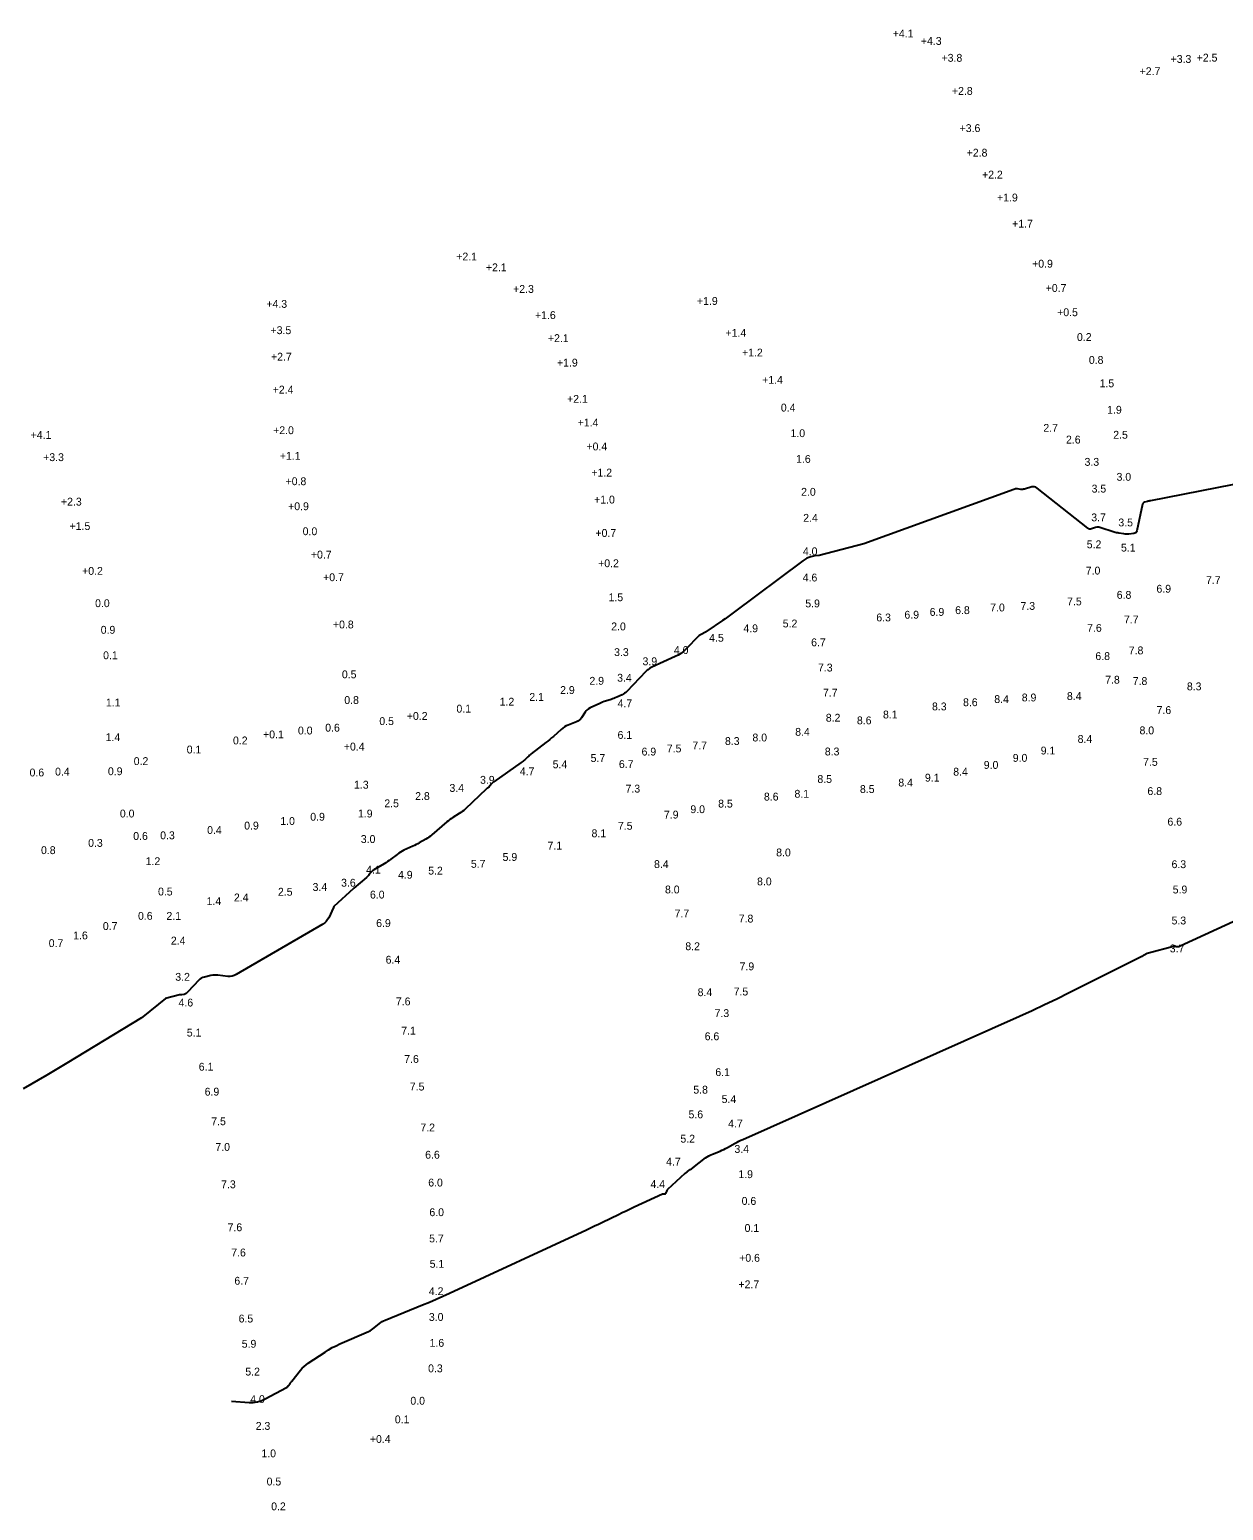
# Model space of a CAD drawing. Extents: x 837127 to 848654, y 3074248 to 3079868.
# Drawn here: x 846810 to 847285, y 3078154 to 3078743 of the extents above; entities that cross this region are included whole.
import ezdxf

# ---------------------------------------------------------------- set-up
doc = ezdxf.new("R2010")
doc.units = 0
doc.layers.add('V-HYDS-MAJR', color=7, linetype='Continuous')
doc.layers.add('V-HYDS-SOUN', color=7, linetype='Continuous')

msp = doc.modelspace()

# ---------------------------------------------------------------- linework, layer by layer
at = {"layer": 'V-HYDS-MAJR'}
for points in [[(847328, 3078569.71), (847255.65, 3078555.5), (847255.34, 3078555.44), (847255.04, 3078555.37), (847254.73, 3078555.3), (847254.43, 3078555.22), (847253.22, 3078554.9), (847252.94, 3078554.79), (847252.73, 3078554.62), (847252.57, 3078554.4), (847252.48, 3078554.12), (847250.14, 3078543.54), (847249.99, 3078543.11), (847249.74, 3078542.79), (847249.39, 3078542.58), (847248.95, 3078542.48), (847246.99, 3078542.28), (847246.5, 3078542.25), (847246.01, 3078542.24), (847245.52, 3078542.27), (847245.03, 3078542.32), (847243.05, 3078542.61), (847242.57, 3078542.69), (847242.08, 3078542.79), (847241.6, 3078542.92), (847241.13, 3078543.06), (847235.44, 3078544.92), (847235.03, 3078545.02), (847234.62, 3078545.05), (847234.21, 3078545.01), (847233.79, 3078544.91), (847232.15, 3078544.35), (847231.74, 3078544.26), (847231.36, 3078544.27), (847230.99, 3078544.39), (847230.64, 3078544.61), (847210.48, 3078560.59), (847209.99, 3078560.9), (847209.46, 3078561.08), (847208.91, 3078561.11), (847208.33, 3078561.01), (847205.48, 3078560.16), (847205.13, 3078560.08), (847204.78, 3078560.03), (847204.43, 3078560.02), (847204.07, 3078560.04), (847202.63, 3078560.21), (847202.27, 3078560.23), (847201.92, 3078560.21), (847201.57, 3078560.15), (847201.23, 3078560.04), (847141.5, 3078538.4), (847123.83, 3078533.73), (847122.06, 3078533.64), (847120.39, 3078533.26), (847118.81, 3078532.6), (847117.32, 3078531.66), (847089.57, 3078510.84), (847088.52, 3078510.06), (847087.46, 3078509.3), (847086.39, 3078508.55), (847085.32, 3078507.81), (847079.01, 3078503.55), (847078.92, 3078503.48), (847078.85, 3078503.4), (847078.79, 3078503.31), (847076.56, 3078502.14), (847076.32, 3078502.03), (847076.09, 3078501.88), (847075.88, 3078501.69), (847070.74, 3078496.42), (847069.79, 3078495.53), (847068.76, 3078494.73), (847067.66, 3078494.04), (847066.49, 3078493.45), (847057.12, 3078489.27), (847056.91, 3078489.17), (847056.7, 3078489.05), (847056.5, 3078488.93), (847056.31, 3078488.79), (847055.55, 3078488.23), (847055.37, 3078488.09), (847055.19, 3078487.93), (847055.02, 3078487.77), (847054.85, 3078487.61), (847047.2, 3078479.63), (847046.78, 3078479.23), (847046.32, 3078478.87), (847045.84, 3078478.56), (847045.32, 3078478.29), (847043.19, 3078477.29), (847042.65, 3078477.05), (847042.11, 3078476.83), (847041.56, 3078476.63), (847041, 3078476.44), (847038.72, 3078475.72), (847038.16, 3078475.54), (847037.6, 3078475.33), (847037.05, 3078475.11), (847036.51, 3078474.86), (847032.6, 3078473.03), (847032.02, 3078472.71), (847031.5, 3078472.32), (847031.03, 3078471.86), (847030.63, 3078471.33), (847029.14, 3078469.09), (847028.74, 3078468.57), (847028.27, 3078468.13), (847027.74, 3078467.76), (847027.14, 3078467.48), (847023.84, 3078466.18), (847023.1, 3078465.86), (847022.4, 3078465.46), (847021.74, 3078465.01), (847021.11, 3078464.5), (847018.02, 3078461.71), (847017.3, 3078461.07), (847016.56, 3078460.44), (847015.82, 3078459.83), (847015.06, 3078459.24), (847009.21, 3078454.74), (847008.87, 3078454.47), (847008.53, 3078454.19), (847008.2, 3078453.9), (847007.88, 3078453.6), (847006.61, 3078452.38), (847006.29, 3078452.09), (847005.95, 3078451.8), (847005.61, 3078451.53), (847005.25, 3078451.27), (846994.26, 3078443.63), (846994.02, 3078443.44), (846993.79, 3078443.24), (846993.57, 3078443.02), (846993.37, 3078442.78), (846992.34, 3078441.46), (846992.28, 3078441.39), (846992.22, 3078441.33), (846992.14, 3078441.28), (846992.06, 3078441.23), (846991.74, 3078441.07), (846991.66, 3078441.03), (846991.58, 3078440.98), (846991.51, 3078440.93), (846991.44, 3078440.87), (846982.88, 3078432.76), (846982.34, 3078432.26), (846981.76, 3078431.8), (846981.17, 3078431.37), (846980.55, 3078430.97), (846978.02, 3078429.42), (846977.4, 3078429.02), (846976.8, 3078428.6), (846976.21, 3078428.15), (846975.64, 3078427.68), (846969.65, 3078422.5), (846969.08, 3078422.03), (846968.49, 3078421.59), (846967.87, 3078421.18), (846967.24, 3078420.8), (846964.66, 3078419.34), (846964.01, 3078418.98), (846963.35, 3078418.63), (846962.69, 3078418.3), (846962.02, 3078417.99), (846958.52, 3078416.38), (846957.81, 3078416.03), (846957.13, 3078415.64), (846956.47, 3078415.21), (846955.83, 3078414.74), (846953.34, 3078412.77), (846952.71, 3078412.29), (846952.06, 3078411.84), (846951.4, 3078411.4), (846950.73, 3078410.99), (846946.55, 3078408.54), (846946.26, 3078408.35), (846945.99, 3078408.14), (846945.73, 3078407.91), (846945.5, 3078407.65), (846944.62, 3078406.58), (846944.4, 3078406.32), (846944.16, 3078406.06), (846943.91, 3078405.82), (846943.65, 3078405.59), (846938.6, 3078401.29), (846938.5, 3078401.19), (846930.69, 3078393.99), (846930.54, 3078393.58), (846928.6, 3078389.51), (846928.17, 3078388.75), (846927.63, 3078388.07), (846927, 3078387.48), (846926.27, 3078386.98), (846891.81, 3078366.86), (846891.01, 3078366.47), (846890.19, 3078366.23), (846889.34, 3078366.12), (846888.46, 3078366.16), (846884.44, 3078366.63), (846883.76, 3078366.68), (846883.09, 3078366.67), (846882.43, 3078366.61), (846881.76, 3078366.48), (846879.12, 3078365.89), (846878.48, 3078365.7), (846877.89, 3078365.42), (846877.35, 3078365.05), (846876.86, 3078364.6), (846872.57, 3078360.01), (846871.86, 3078359.39), (846871.07, 3078358.99), (846870.21, 3078358.79), (846869.27, 3078358.81), (846863.67, 3078357.41), (846854.7, 3078350.03), (846854.07, 3078349.69), (846824.44, 3078331.58), (846822.44, 3078330.37), (846820.44, 3078329.17), (846818.42, 3078327.99), (846816.4, 3078326.83), (846807, 3078321.46)], [(846889.87, 3078197.11), (846896.9, 3078196.56), (846898.58, 3078196.55), (846900.2, 3078196.77), (846901.77, 3078197.23), (846903.29, 3078197.92), (846911.78, 3078202.52), (846912.02, 3078202.66), (846912.24, 3078202.83), (846912.44, 3078203.02), (846912.61, 3078203.24), (846913.29, 3078204.13), (846913.46, 3078204.36), (846913.63, 3078204.58), (846913.8, 3078204.8), (846913.97, 3078205.02), (846917.44, 3078209.42), (846918.1, 3078210.19), (846918.82, 3078210.91), (846919.59, 3078211.57), (846920.42, 3078212.16), (846927.15, 3078216.63), (846928.57, 3078217.53), (846930.03, 3078218.36), (846931.53, 3078219.13), (846933.06, 3078219.84), (846944.5, 3078224.79), (846945.1, 3078225.08), (846945.67, 3078225.41), (846946.22, 3078225.79), (846946.74, 3078226.2), (846948.76, 3078227.95), (846949.28, 3078228.37), (846949.83, 3078228.74), (846950.41, 3078229.06), (846951.02, 3078229.33), (846965.97, 3078235.38), (846968.67, 3078236.49), (846971.35, 3078237.63), (846974.01, 3078238.8), (846976.66, 3078240.01), (847031.21, 3078265.33), (847032.79, 3078266.07), (847034.38, 3078266.82), (847035.96, 3078267.57), (847037.54, 3078268.33), (847043.86, 3078271.38), (847045.44, 3078272.13), (847047.03, 3078272.88), (847048.61, 3078273.63), (847050.2, 3078274.37), (847061.48, 3078279.59), (847061.58, 3078279.63), (847061.69, 3078279.65), (847061.8, 3078279.66), (847061.91, 3078279.66), (847062.38, 3078279.6), (847062.48, 3078279.6), (847062.57, 3078279.63), (847062.64, 3078279.68), (847062.7, 3078279.76), (847062.92, 3078280.12), (847062.98, 3078280.21), (847063.03, 3078280.31), (847063.07, 3078280.4), (847063.11, 3078280.5), (847063.31, 3078280.99), (847063.36, 3078281.1), (847063.42, 3078281.21), (847063.49, 3078281.3), (847063.58, 3078281.39), (847070.46, 3078287.76), (847070.7, 3078287.97), (847070.94, 3078288.17), (847071.18, 3078288.36), (847071.44, 3078288.54), (847072.47, 3078289.25), (847072.72, 3078289.43), (847072.98, 3078289.61), (847073.23, 3078289.8), (847073.48, 3078289.99), (847078.6, 3078293.88), (847079.25, 3078294.34), (847079.93, 3078294.76), (847080.63, 3078295.13), (847081.36, 3078295.45), (847084.33, 3078296.65), (847085.07, 3078296.97), (847085.8, 3078297.3), (847086.52, 3078297.65), (847087.23, 3078298.03), (847090.33, 3078299.73), (847091.08, 3078300.14), (847091.85, 3078300.53), (847092.62, 3078300.9), (847093.4, 3078301.26), (847203.53, 3078350.37), (847208.5, 3078352.62), (847213.45, 3078354.93), (847218.36, 3078357.29), (847223.25, 3078359.7), (847252.14, 3078374.19), (847252.33, 3078374.28), (847252.52, 3078374.38), (847252.7, 3078374.48), (847252.89, 3078374.59), (847253.62, 3078375.01), (847253.81, 3078375.12), (847253.99, 3078375.22), (847254.17, 3078375.33), (847254.35, 3078375.45), (847265.27, 3078378.33), (847265.81, 3078378.13), (847266.35, 3078378.07), (847266.89, 3078378.13), (847267.44, 3078378.32), (847300.09, 3078393.35)]]:
    msp.add_lwpolyline(points, dxfattribs=at)

# ---------------------------------------------------------------- texts
at = {"layer": 'V-HYDS-SOUN'}
for s, p in [('+4.1 ', (847153.06, 3078739.96)), ('+4.3 ', (847164.24, 3078737)), ('+3.8 ', (847172.47, 3078730.29)), ('+3.3 ', (847263.61, 3078729.83)), ('+2.5 ', (847274, 3078730.36)), ('+2.7 ', (847251.29, 3078724.96)), ('+2.8 ', (847176.61, 3078717.11)), ('+3.6 ', (847179.66, 3078702.3)), ('+2.8 ', (847182.47, 3078692.52)), ('+2.2 ', (847188.59, 3078683.79)), ('+1.9 ', (847194.55, 3078674.68)), ('+1.7 ', (847200.56, 3078664.24)), ('+2.1 ', (846979.36, 3078651.17)), ('+2.1 ', (846991.16, 3078646.86)), ('+0.9 ', (847208.52, 3078648.33)), ('+2.3 ', (847001.99, 3078638.28)), ('+1.9 ', (847075.15, 3078633.5)), ('+0.7 ', (847213.9, 3078638.66)), ('+4.3 ', (846903.81, 3078632.33)), ('+1.6 ', (847010.69, 3078627.85)), ('+0.5 ', (847218.48, 3078629.01)), ('+3.5 ', (846905.46, 3078621.86)), ('+2.1 ', (847015.84, 3078618.7)), ('+1.4 ', (847086.5, 3078620.79)), ('0.2', (847226.36, 3078619.13)), ('+2.7 ', (846905.65, 3078611.3)), ('+1.2 ', (847093.08, 3078612.96)), ('0.8', (847231.09, 3078610.02)), ('+1.9 ', (847019.45, 3078608.94)), ('+2.4 ', (846906.32, 3078598.2)), ('+1.4 ', (847101.09, 3078602.07)), ('1.5', (847235.36, 3078600.71)), ('+2.1 ', (847023.45, 3078594.51)), ('0.4', (847108.52, 3078591.04)), ('1.9', (847238.37, 3078590.17)), ('+4.1 ', (846810, 3078580.17)), ('+2.0 ', (846906.5, 3078582.03)), ('+1.4 ', (847027.68, 3078585.09)), ('1.0', (847112.37, 3078580.85)), ('2.7', (847212.98, 3078582.97)), ('2.5', (847240.79, 3078580.22)), ('+0.4 ', (847031.18, 3078575.57)), ('2.6', (847221.99, 3078578.3)), ('+3.3 ', (846814.99, 3078571.31)), ('+1.1 ', (846909.15, 3078571.84)), ('1.6', (847114.59, 3078570.62)), ('3.3', (847229.37, 3078569.44)), ('+1.2 ', (847033.12, 3078565.17)), ('3.0', (847242.11, 3078563.48)), ('+0.8 ', (846911.44, 3078561.72)), ('2.0', (847116.59, 3078557.51)), ('3.5', (847232.18, 3078558.78)), ('+2.3 ', (846822.07, 3078553.6)), ('+0.9 ', (846912.46, 3078551.77)), ('+1.0 ', (847034.22, 3078554.42)), ('2.4', (847117.42, 3078547.15)), ('3.7', (847232.05, 3078547.33)), ('3.5', (847242.83, 3078545.31)), ('+1.5 ', (846825.48, 3078543.87)), (' 0.0', (846917.08, 3078541.81)), ('+0.7 ', (847034.75, 3078541.13)), ('4.0', (847117.28, 3078533.83)), ('5.2', (847230.25, 3078536.61)), ('5.1', (847243.87, 3078535.3)), ('+0.7 ', (846921.52, 3078532.51)), ('+0.2 ', (847035.82, 3078529.07)), ('+0.2 ', (846830.48, 3078526.03)), ('+0.7 ', (846926.37, 3078523.51)), ('4.6', (847117.22, 3078523.39)), ('7.0', (847229.86, 3078526.15)), ('7.7', (847277.7, 3078522.37)), ('1.5', (847039.96, 3078515.54)), ('6.8', (847242.18, 3078516.49)), ('6.9', (847257.99, 3078518.93)), (' 0.0', (846834.48, 3078513.17)), ('5.9', (847118.25, 3078513.08)), ('6.9', (847167.74, 3078509.7)), ('6.8', (847177.89, 3078510.4)), ('7.0', (847191.83, 3078511.47)), ('7.3', (847203.88, 3078512.09)), ('7.5', (847222.43, 3078513.87)), ('+0.8 ', (846930.29, 3078504.7)), ('2.0', (847041.02, 3078503.92)), ('4.9', (847093.63, 3078503.17)), ('5.2', (847109.28, 3078505.09)), ('6.3', (847146.51, 3078507.49)), ('6.9', (847157.7, 3078508.59)), ('7.6', (847230.4, 3078503.35)), ('7.7', (847245.05, 3078506.66)), ('0.9', (846837.88, 3078502.57)), ('4.5', (847080, 3078499.41)), ('6.7', (847120.58, 3078497.6)), ('0.1', (846838.83, 3078492.43)), ('3.3', (847042.17, 3078493.69)), ('4.0', (847065.97, 3078494.53)), ('6.8', (847233.69, 3078492.1)), ('7.8', (847246.97, 3078494.37)), ('3.9', (847053.48, 3078490.04)), ('7.3', (847123.31, 3078487.55)), ('0.5', (846933.85, 3078484.85)), ('2.9', (847032.35, 3078482.27)), ('3.4', (847043.38, 3078483.48)), ('7.8', (847237.59, 3078482.7)), ('7.8', (847248.54, 3078482.17)), ('8.3', (847270.09, 3078480.06)), ('0.8', (846934.81, 3078474.62)), ('1.2', (846996.63, 3078473.96)), ('2.1', (847008.43, 3078475.86)), ('2.9', (847020.69, 3078478.6)), ('7.7', (847125.28, 3078477.57)), ('8.6', (847181.02, 3078473.74)), ('8.4', (847193.45, 3078474.99)), ('8.9', (847204.39, 3078475.64)), ('8.4', (847222.36, 3078476.2)), ('1.1', (846839.94, 3078473.63)), ('+0.2 ', (846959.69, 3078468.27)), ('0.1', (846979.43, 3078471.18)), ('4.7', (847043.54, 3078473.31)), ('8.1', (847149.17, 3078468.86)), ('8.3', (847168.67, 3078472.07)), ('7.6', (847258.04, 3078470.62)), (' 0.0', (846915.2, 3078462.48)), ('0.6', (846927.21, 3078463.61)), ('0.5', (846948.75, 3078466.22)), ('8.4', (847114.23, 3078461.96)), ('8.2', (847126.41, 3078467.57)), ('8.6', (847138.8, 3078466.52)), ('8.0', (847251.25, 3078462.54)), ('1.4', (846839.84, 3078459.83)), ('0.2', (846890.51, 3078458.53)), ('+0.1 ', (846902.48, 3078460.93)), ('+0.4 ', (846934.63, 3078456.08)), ('6.1', (847043.54, 3078460.72)), ('7.7', (847073.32, 3078456.52)), ('8.3', (847086.29, 3078458.29)), ('8.0', (847097.22, 3078459.7)), ('8.4', (847226.63, 3078459.13)), ('0.2', (846851.01, 3078450.3)), ('0.1', (846872.1, 3078454.92)), ('5.7', (847032.83, 3078451.54)), ('6.9', (847053.09, 3078454.09)), ('7.5', (847063.14, 3078455.34)), ('8.3', (847126.02, 3078454.13)), ('9.0', (847200.8, 3078451.6)), ('9.1', (847211.92, 3078454.52)), ('0.6', (846809.56, 3078445.78)), ('0.4', (846819.72, 3078446.12)), ('0.9', (846840.75, 3078446.26)), ('4.7', (847004.65, 3078446.23)), ('5.4', (847017.73, 3078449.03)), ('6.7', (847044.08, 3078449.12)), ('8.4', (847177.11, 3078446.09)), ('9.0', (847189.27, 3078448.78)), ('7.5', (847252.67, 3078450)), ('1.3', (846938.68, 3078440.9)), ('3.4', (846976.66, 3078439.62)), ('3.9', (846988.84, 3078442.85)), ('7.3', (847046.73, 3078439.35)), ('8.5', (847123.07, 3078443.18)), ('8.5', (847140, 3078439.19)), ('8.4', (847155.27, 3078441.77)), ('9.1', (847165.86, 3078443.71)), ('6.8', (847254.4, 3078438.36)), ('2.5', (846950.74, 3078433.5)), ('2.8', (846963.01, 3078436.38)), ('8.5', (847083.57, 3078433.39)), ('8.6', (847101.79, 3078436.17)), ('8.1', (847113.94, 3078437.29)), (' 0.0', (846844.34, 3078429.43)), ('0.9', (846921.26, 3078428.15)), ('1.9', (846940.24, 3078429.44)), ('7.9', (847062, 3078429)), ('9.0', (847072.52, 3078431.16)), ('0.3', (846861.54, 3078420.76)), ('0.4', (846880.22, 3078422.86)), ('0.9', (846894.97, 3078424.62)), ('1.0', (846909.35, 3078426.45)), ('8.1', (847033.19, 3078421.57)), ('7.5', (847043.7, 3078424.55)), ('6.6', (847262.37, 3078426.19)), ('0.8', (846814.12, 3078414.85)), ('0.3', (846832.87, 3078417.74)), ('0.6', (846850.81, 3078420.48)), ('3.0', (846941.37, 3078419.28)), ('7.1', (847015.68, 3078416.68)), ('1.2', (846855.78, 3078410.46)), ('5.7', (846985.17, 3078409.41)), ('5.9', (846997.8, 3078412.14)), ('8.4', (847058.06, 3078409.3)), ('8.0', (847106.67, 3078413.94)), ('6.3', (847263.99, 3078409.26)), ('4.1', (846943.48, 3078407.08)), ('4.9', (846956.17, 3078405.05)), ('5.2', (846968.19, 3078406.69)), ('0.5', (846860.69, 3078398.38)), ('2.5', (846908.41, 3078398.29)), ('3.4', (846922.19, 3078400.19)), ('3.6', (846933.53, 3078401.89)), ('6.0', (846945.02, 3078397.15)), ('8.0', (847062.42, 3078399.2)), ('8.0', (847099.06, 3078402.4)), ('5.9', (847264.46, 3078399.19)), ('1.4', (846880, 3078394.57)), ('2.4', (846890.89, 3078396.02)), ('0.6', (846852.72, 3078388.7)), ('2.1', (846864.04, 3078388.68)), ('6.9', (846947.49, 3078385.81)), ('7.7', (847066.24, 3078389.65)), ('7.8', (847091.77, 3078387.62)), ('5.3', (847263.99, 3078386.85)), ('1.6', (846826.92, 3078380.9)), ('0.7', (846838.73, 3078384.64)), ('0.7', (846817.19, 3078377.84)), ('2.4', (846865.79, 3078378.86)), ('8.2', (847070.52, 3078376.6)), ('3.7', (847263.29, 3078375.73)), ('6.4', (846951.25, 3078371.24)), ('7.9', (847092.1, 3078368.6)), ('3.2', (846867.56, 3078364.42)), ('8.4', (847075.41, 3078358.3)), ('7.5', (847089.74, 3078358.57)), ('4.6', (846868.85, 3078354.18)), ('7.6', (846955.33, 3078354.64)), ('7.3', (847082.16, 3078349.97)), ('5.1', (846872.14, 3078342.23)), ('7.1', (846957.48, 3078342.99)), ('6.6', (847078.21, 3078340.75)), ('6.1', (846876.9, 3078328.63)), ('7.6', (846958.65, 3078331.72)), ('6.1', (847082.46, 3078326.48)), ('7.5', (846960.88, 3078320.74)), ('6.9', (846879.24, 3078318.71)), ('5.8', (847073.69, 3078319.49)), ('5.4', (847084.95, 3078315.75)), ('5.6', (847071.78, 3078309.67)), ('7.5', (846881.88, 3078306.92)), ('7.2', (846965.09, 3078304.45)), ('4.7', (847087.55, 3078306.01)), ('5.2', (847068.56, 3078299.99)), ('7.0', (846883.51, 3078296.71)), ('6.6', (846966.99, 3078293.6)), ('3.4', (847090.06, 3078295.89)), ('4.7', (847062.86, 3078290.86)), ('1.9', (847091.62, 3078285.85)), ('7.3', (846885.8, 3078281.83)), ('6.0', (846968.21, 3078282.52)), ('4.4', (847056.65, 3078281.93)), ('0.6', (847092.92, 3078275.2)), ('6.0', (846968.67, 3078270.72)), ('7.6', (846888.37, 3078264.72)), ('0.1', (847094.1, 3078264.43)), ('5.7', (846968.57, 3078260.26)), ('7.6', (846889.82, 3078254.67)), ('5.1', (846968.79, 3078250.18)), ('+0.6 ', (847091.95, 3078252.55)), ('6.7', (846891.08, 3078243.42)), ('4.2', (846968.45, 3078239.27)), ('+2.7 ', (847091.66, 3078242.01)), ('6.5', (846892.76, 3078228.38)), ('3.0', (846968.47, 3078229.01)), ('5.9', (846894, 3078218.33)), ('1.6', (846968.74, 3078218.7)), ('0.3', (846968.15, 3078208.56)), ('5.2', (846895.43, 3078207.26)), ('4.0', (846897.37, 3078196.3)), (' 0.0', (846959.94, 3078195.66)), ('2.3', (846899.56, 3078185.64)), ('0.1', (846954.91, 3078188.25)), ('+0.4 ', (846944.99, 3078180.43)), ('1.0', (846901.82, 3078174.71)), ('0.5', (846903.91, 3078163.5)), ('0.2', (846905.71, 3078153.62))]:
    msp.add_text(s, height=3.125, dxfattribs=at).set_placement(p)

doc.saveas('drawing.dxf')
